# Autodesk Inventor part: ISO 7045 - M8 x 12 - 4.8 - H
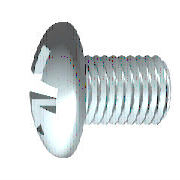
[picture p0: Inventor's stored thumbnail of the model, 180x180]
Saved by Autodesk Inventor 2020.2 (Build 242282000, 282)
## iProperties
Created: 2019-01
Part Number: ISO 7045 - M8 x 12 - 4.8 - H
Material: Stal
Description: Wkręt
Document SubType Name: Modeling
Standard: ISO 7045
Designer: F.Stasiak
Standard Revision: Third edition 2011-09-01
Standards Organization: ISO
Language: pl-PL
Size Designation: M8 x 12 - 4.8 - H
Categories: <MemberInstance><Categories><Category DisplayName="Mocowania" InternalName="e4da775c-781d-43d5-af7c-5136215cf5a6" Mnemonic="FSTN"><Category DisplayName="Śruby"
Density: 7.85 g/cm^3
Appearance: Płyta
Manager: www.cadconsulting.pl
Company: Fabian Stasiak CAD Consulting
IsCustomPart: 0
Author: F.Stasiak
Subject: Zbiór ćwiczeń. Autodesk Inventor 2020. Kurs podstawowy
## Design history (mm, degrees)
body "Solid1"
workplane "Work Plane3"
sketch "Szkic2"
  geometry: L1 (-11.037, 0)-(11.037, 0) reference; L2 (0, -11.037)-(0, 11.037) reference; L3 (0, 4.5)-(0, 0); L4 (0, 0)-(4.5, 0); L5 (0, 0)-(5.574, 5.574); L6 (1.21, 4.334)-(0.822, 1.343); L7 (4.334, 1.21)-(1.343, 0.822); L8 (1.21, -4.334)-(0.822, -1.343); L9 (4.334, -1.21)-(1.343, -0.822); L10 (-1.21, 4.334)-(-0.822, 1.343); L11 (-4.334, 1.21)-(-1.343, 0.822); L12 (-4.334, -1.21)-(-1.343, -0.822); L13 (-1.21, -4.334)-(-0.822, -1.343); A1 r 1.35 centre (0, 0) between (1.35, 0) and (0, 1.35); A2 r 4.5 centre (0, 0) between (4.5, 0) and (4.334, 1.21); A3 r 4.5 centre (0, 0) between (1.21, 4.334) and (0, 4.5); A4 r 4.5 centre (0, 0) between (4.334, 1.21) and (1.21, 4.334); A5 r 4.5 centre (0, 0) between (0, -4.5) and (1.21, -4.334); A6 r 4.5 centre (0, 0) between (1.21, -4.334) and (4.334, -1.21); A7 r 4.5 centre (0, 0) between (4.334, -1.21) and (4.5, 0); A8 r 4.5 centre (0, 0) between (-4.334, 1.21) and (-4.5, 0); A9 r 4.5 centre (0, 0) between (-1.21, 4.334) and (-4.334, 1.21); A10 r 4.5 centre (0, 0) between (0, 4.5) and (-1.21, 4.334); A11 r 4.5 centre (0, 0) between (-4.5, 0) and (-4.334, -1.21); A12 r 4.5 centre (0, 0) between (-4.334, -1.21) and (-1.21, -4.334); A13 r 4.5 centre (0, 0) between (-1.21, -4.334) and (0, -4.5); A14 r 1.575 centre (0, 0) between (1.575, 0) and (0, 1.575); A15 r 0.465 centre (1.284, 1.284) between (0.822, 1.343) and (1.343, 0.822); A16 r 0.465 centre (1.284, -1.284) between (1.343, -0.822) and (0.822, -1.343); A17 r 0.465 centre (-1.284, 1.284) between (-1.343, 0.822) and (-0.822, 1.343); A18 r 0.465 centre (-1.284, -1.284) between (-0.822, -1.343) and (-1.343, -0.822); 1 further point
  constraints: 38 point on circle, 22 end point, 19 symmetric about line, 18 centre point, 4 coincident, 3 collinear, 3 point on line, 3 tangent, 1 perpendicular, 21 other
  dimensions: "d4" = 45 deg angle of L5 L4; "d5" = 2.7 diameter of A1 (= 0.3 x SDM); "d6" = 9 diameter of A4 (= SDM); "d7" = 1.21 distance from line of L6.start L3 (= 0.5 x SBR); "d14" = 3.15 diameter of A14 (= 0.35 x SDM)
extrude "Szczelina" join sketch "Szkic2" taper "d15" = 5 deg; stored distance "d54" = 10
revolve "Wycięcie" stored, may be unused: angle "d56" = 90 deg
revolve "Bryła" stored, may be unused: angle "d18" = 90 deg
workplane "Work Plane1"
sketch "Szkic1"
  geometry: L1 (12, 0)-(12, 4); L2 (12, 4)-(2.5, 4); L3 (3.962, 5.08)-(3.962, 5.08); L4 (-6, 0)-(-6, 7.79); L5 (-5.317, 4.159)-(-2.996, 3.002); L6 (-2.996, 3.002)-(-1.4, 0); L7 (-1.4, 0)-(12, 0); L8 (-10.377, 0)-(15.73, 0) reference; L9 (0, -1.62)-(0, 9.723) reference; L10 (-5.317, 4.159)-(-6, 4.5); L11 (-3.337, 7.883)-(-6, 7.79); L12 (-3.337, 7.883)-(0, 8); L13 (0, 8)-(0, 3.662); L14 (0, 3.662)-(1.733, 3.662); L15 (1.733, 3.662)-(2.5, 4); L16 (2.5, 4)-(0, 4); A1 r 13 centre (7, 0) between (-3.337, 7.883) and (-6, 0)
  constraints: 28 end point, 5 point on line, 4 collinear, 4 point on circle, 3 parallel, 2 perpendicular, 1 centre point, 1 horizontal, 1 tangent
  dimensions: "d1" = 8 diameter of L2 L7 (= GD); "d2" = 4.6 distance from line of L6.end L4 (= STI); "d11" = 9 diameter of L10.end L7 (= SDM); "d12" = 62 deg angle of L6 L7; "d13" = 26.5 deg angle of L5 L7; "d17" = 16 diameter of L12.end L7 (= KOD); "d19" = 2 deg angle of L12 L7 (= KEWI); "d20" = 6 distance between parallel lines of L4 L13 (= KOH); "d21" = 13 radius of A1 (= KR); "d23" = 7.32342 diameter of L14 L7 (= BDM); "d24" = 9.5 distance of L1.end L2.end (= GEL); "d25" = 0.76681 horizontal distance of L14.end L2.end (= GAL); "d28" = 12 distance between parallel lines of L1 L13 (= NLG)
fillet "Zaokrąglenie1" dims "d29" = 2.6 (= RR)
fillet "Zaokrąglenie2" dims "d16" = 0.484 (= 0.2 x SBR)
feature "Gwint" dims "d8" = 9.5 (= GEL), "d9" = 0
chamfer "Faza1" distance "d26" = 0.76681 (= -0.5 x SPD + 0.5 x GD); stored, may be unused: second distance "d27" = 0.76691 (computed from GUL), angle "d78" = 45 deg
other parameters: "GD" = 8 [user parameter; used in 2 equation terms], "NLG" = 12 [user parameter; used in 1 equation term], "GEL" = 9.5 [user parameter; used in 2 equation terms], "KOD" = 16 [user parameter; used in 1 equation term], "KOH" = 6 [user parameter; used in 2 equation terms], "SDM" = 9 [user parameter; used in 4 equation terms], "STI" = 4.6 [user parameter; used in 1 equation term], "SBR" = 2.42 [user parameter; used in 2 equation terms], "GAL" = 0.76681 (= 0.61345 x PTC) [user parameter; used in 1 equation term], "SPD" = 6.46637 (= NND - 1.2269 x PTC) [user parameter; used in 1 equation term], "KEWI" = 2 deg [user parameter; used in 1 equation term], "d3" = -6 (= -KOH), "d10" = 0, "KR" = 13 [user parameter; used in 1 equation term], "BDM" = 7.32342 [user parameter; used in 1 equation term], "GUL" = 0.76681 (= 0.61345 x PTC) [user parameter; used in 1 equation term], "RR" = 2.6 [user parameter; used in 1 equation term], "d79" = 0, "d80" = 0, "PTC" = 1.25 [user parameter; used in 5 equation terms], "THREADDIA" = 8 [user parameter; used in 1 equation term], "TOA" = 30 deg [user parameter], "TPU" = 8 (computed from PTC) [user parameter], "NND" = 8 [user parameter; used in 1 equation term], "GD1" = 6.46637 (= THREADDIA - 1.2269 x PTC) [user parameter]
